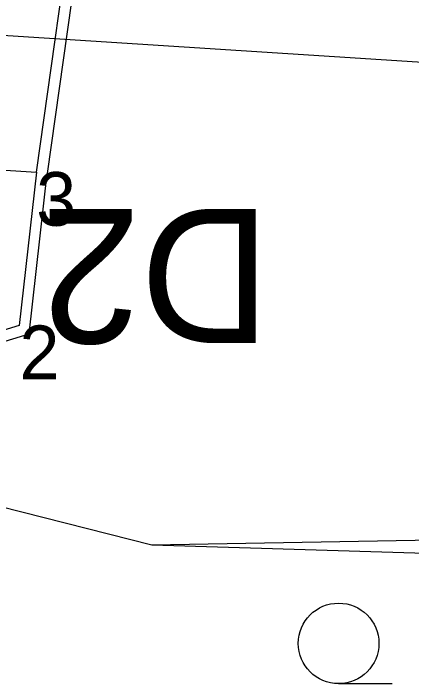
# Model space of a CAD drawing. Extents: x -728800 to -728100, y -1073200 to -1072700.
# Drawn here: x -728494.54 to -728487.13, y -1073056.02 to -1073043.53 of the extents above; entities that cross this region are included whole.
import ezdxf

# ---------------------------------------------------------------- set-up
doc = ezdxf.new("R2010")
doc.units = 0
for name, color, linetype in [('A1_OBVOD Spravy železnic', 7, 'Continuous'), ('A2_OBVOD STAVBY', 7, 'Continuous'), ('B1_body_poloha', 7, 'Continuous'), ('B2_body_číslo', 7, 'Continuous'), ('B6_JŽM', 7, 'Continuous'), ('K_01_Hranice parcel', 7, 'Continuous'), ('K_03_Značky druhu pozemku', 7, 'Continuous'), ('ZA_02_Dočasný_do_1_roku', 7, 'Continuous')]:
    doc.layers.add(name, color=color, linetype=linetype)

msp = doc.modelspace()

# ---------------------------------------------------------------- linework, layer by layer
at = {"layer": 'A1_OBVOD Spravy železnic'}
msp.add_lwpolyline([(-728503.24, -1073052.34), (-728499.33, -1073052.26), (-728496.81, -1073052.21), (-728491.97, -1073053.44), (-728470.97, -1073054.08), (-728434.43, -1073049.27), (-728361.73, -1073039.5), (-728349.166, -1073038.984)], dxfattribs=at)
at = {"layer": 'A2_OBVOD STAVBY'}
for points in [[(-728488.873, -1073026.674), (-728487.617, -1073033.578), (-728488.418, -1073038.141), (-728493.164, -1073041.187), (-728493.918, -1073046.515)], [(-728503.756, -1073049.547), (-728504.358, -1073053.426), (-728503.463, -1073053.572), (-728499.628, -1073054.199), (-728499.129, -1073052.28), (-728499.2, -1073051.021), (-728494.25, -1073049.503), (-728493.918, -1073046.515)]]:
    msp.add_lwpolyline(points, dxfattribs=at)
at = {"layer": 'B1_body_poloha'}
for p, q in [((-728494.12, -1073046.49), (-728494.12, -1073046.49)), ((-728494.43, -1073049.35), (-728494.43, -1073049.35))]:
    msp.add_line(p, q, dxfattribs=at)
at = {"layer": 'B6_JŽM'}
msp.add_lwpolyline([(-728300.809, -1073024.355), (-728320.8, -1073026.914), (-728374.008, -1073033.722), (-728429.095, -1073040.747), (-728461.932, -1073044.273), (-728481.199, -1073044.815), (-728499.353, -1073043.648), (-728506.01, -1073042.737), (-728514.574, -1073041.329), (-728535.848, -1073035.998), (-728561.353, -1073026.113), (-728583.963, -1073013.524), (-728603.757, -1072998.891), (-728619.185, -1072984.418), (-728634.193, -1072966.825), (-728646.078, -1072949.194), (-728656.182, -1072930.072), (-728664.987, -1072910.227), (-728668.627, -1072901.808), (-728681.252, -1072876.016), (-728691.886, -1072859.663)], dxfattribs=at)
at = {"layer": 'K_01_Hranice parcel'}
msp.add_lwpolyline([(-728496.81, -1073052.21), (-728491.97, -1073053.44), (-728477.97, -1073053.19)], dxfattribs=at)
at = {"layer": 'K_03_Značky druhu pozemku'}
msp.add_line((-728488.492, -1073056.024), (-728487.492, -1073056.024), dxfattribs=at)
msp.add_circle((-728488.492, -1073055.274), 0.75, dxfattribs=at)
at = {"layer": 'ZA_02_Dočasný_do_1_roku'}
for points in [[(-728501.19, -1073037.94), (-728502.042, -1073043.972), (-728498.502, -1073044.372), (-728498.756, -1073046.192), (-728494.117, -1073046.49), (-728493.349, -1073041.068)], [(-728502.83, -1073049.48), (-728502.042, -1073043.972), (-728498.502, -1073044.372), (-728498.756, -1073046.192), (-728494.117, -1073046.49), (-728494.434, -1073049.35), (-728499.408, -1073050.876), (-728499.33, -1073052.26)]]:
    msp.add_lwpolyline(points, dxfattribs=at)

# ---------------------------------------------------------------- texts
at = {"layer": 'B2_body_číslo'}
for s, p in [('3', (-728494.12, -1073047.49)), ('2', (-728494.43, -1073050.35))]:
    msp.add_text(s, height=1, dxfattribs=at).set_placement(p)
at = {"layer": 'ZA_02_Dočasný_do_1_roku'}
msp.add_text('D2', height=2.5, rotation=180, dxfattribs=at).set_placement((-728489.761, -1073047.178))

doc.saveas('drawing.dxf')
